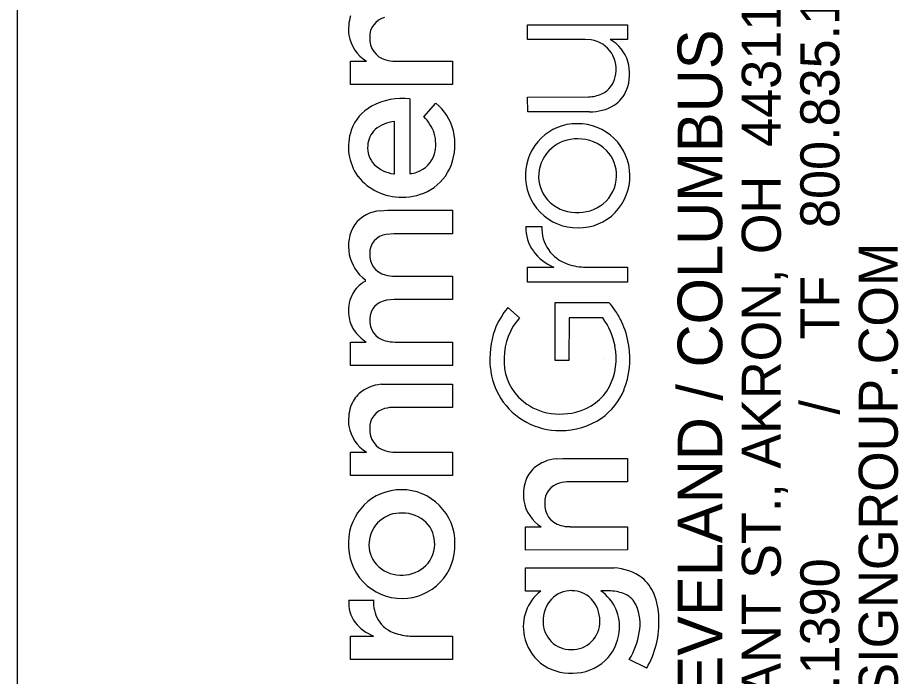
# Model space of a CAD drawing. Extents: x 0 to 34, y 0 to 22.
# Drawn here: x 32 to 33.125, y 3.094 to 3.936 of the extents above; entities that cross this region are included whole.
import ezdxf

# ---------------------------------------------------------------- set-up
doc = ezdxf.new("R2010")
doc.units = 0
doc.layers.add('SH_Border', color=7, linetype='Continuous')
doc.layers.add('SH_Data', color=7, linetype='Continuous')

msp = doc.modelspace()

# ---------------------------------------------------------------- linework, layer by layer
at = {"layer": 'SH_Border'}
msp.add_line((32, 0.5), (32, 21.5), dxfattribs=at)
at = {"layer": 'SH_Data'}
for p, q in [((32.6515, 3.908), (32.6515, 3.9267)), ((32.6515, 3.9267), (32.7791, 3.9266)), ((32.7791, 3.9266), (32.7791, 3.908)), ((32.7249, 3.908), (32.6515, 3.908)), ((32.7328, 3.9073), (32.7249, 3.908)), ((32.7791, 3.908), (32.7569, 3.908)), ((32.4254, 3.8503), (32.4254, 3.8802)), ((32.4254, 3.8802), (32.4455, 3.8802)), ((32.4822, 3.8802), (32.5557, 3.8802)), ((32.5557, 3.8802), (32.5557, 3.8504)), ((32.5557, 3.8504), (32.4254, 3.8503)), ((32.5011, 3.8321), (32.5012, 3.7366)), ((32.5188, 3.8093), (32.5342, 3.8266)), ((32.6515, 3.8344), (32.7291, 3.8345)), ((32.6517, 3.8154), (32.6515, 3.8344)), ((32.7307, 3.8154), (32.6517, 3.8154)), ((32.4814, 3.7364), (32.4814, 3.803)), ((32.4802, 3.7363), (32.4814, 3.7364)), ((32.4633, 3.6891), (32.4726, 3.6897)), ((32.4726, 3.6897), (32.5556, 3.6897)), ((32.5556, 3.6897), (32.5557, 3.6598)), ((32.6493, 3.6691), (32.6698, 3.6691)), ((32.4806, 3.6598), (32.471, 3.6588)), ((32.5557, 3.6598), (32.4806, 3.6598)), ((32.6515, 3.598), (32.6515, 3.617)), ((32.6515, 3.617), (32.6848, 3.617)), ((32.726, 3.617), (32.7791, 3.617)), ((32.7791, 3.617), (32.779, 3.598)), ((32.4444, 3.5992), (32.4446, 3.6007)), ((32.4822, 3.6055), (32.5557, 3.6055)), ((32.5557, 3.6055), (32.5557, 3.5757)), ((32.779, 3.598), (32.6515, 3.598)), ((32.4809, 3.5757), (32.4714, 3.5747)), ((32.5557, 3.5757), (32.4809, 3.5757)), ((32.6868, 3.5718), (32.7552, 3.5719)), ((32.6868, 3.4978), (32.6868, 3.5718)), ((32.6264, 3.5655), (32.6411, 3.5524)), ((32.7045, 3.5524), (32.7043, 3.4978)), ((32.7474, 3.5523), (32.7045, 3.5524)), ((32.4254, 3.4915), (32.4254, 3.5214)), ((32.4254, 3.5214), (32.4451, 3.5214)), ((32.4821, 3.5214), (32.5557, 3.5214)), ((32.5557, 3.5214), (32.5557, 3.4916)), ((32.75, 3.5), (32.75, 3.5)), ((32.5557, 3.4916), (32.4254, 3.4915)), ((32.7043, 3.4978), (32.6868, 3.4978)), ((32.4644, 3.4674), (32.4729, 3.4678)), ((32.4729, 3.4678), (32.5557, 3.4678)), ((32.5557, 3.4678), (32.5557, 3.438)), ((32.5557, 3.438), (32.4814, 3.438)), ((32.4254, 3.3509), (32.4254, 3.3807)), ((32.4254, 3.3807), (32.4455, 3.3807)), ((32.4822, 3.3807), (32.5557, 3.3807)), ((32.5557, 3.3807), (32.5557, 3.351)), ((32.6878, 3.3722), (32.6963, 3.3727)), ((32.6963, 3.3727), (32.7792, 3.3727)), ((32.7792, 3.3727), (32.7792, 3.3429)), ((32.5557, 3.351), (32.4254, 3.3509)), ((32.7792, 3.3429), (32.7048, 3.3428)), ((32.6489, 3.2557), (32.6489, 3.2855)), ((32.6489, 3.2855), (32.669, 3.2855)), ((32.7057, 3.2855), (32.7791, 3.2855)), ((32.7791, 3.2855), (32.7792, 3.2558)), ((32.7792, 3.2558), (32.6489, 3.2557)), ((32.6489, 3.2034), (32.6489, 3.2332)), ((32.6489, 3.2332), (32.7524, 3.2332)), ((32.7524, 3.2332), (32.7619, 3.2329)), ((32.6684, 3.2034), (32.6489, 3.2034)), ((32.7576, 3.2036), (32.7449, 3.2036)), ((32.423, 3.1919), (32.4545, 3.1919)), ((32.4254, 3.1159), (32.4254, 3.1458)), ((32.4254, 3.1458), (32.4547, 3.1458)), ((32.5041, 3.1458), (32.5557, 3.1457)), ((32.5557, 3.1457), (32.5556, 3.1159)), ((32.5556, 3.1159), (32.4254, 3.1159)), ((32.8036, 3.1049), (32.7812, 3.116))]:
    msp.add_line(p, q, dxfattribs=at)
for points in [[(32.7328, 3.9073), (32.7249, 3.908), (32.6515, 3.908), (32.6515, 3.9267), (32.7791, 3.9266), (32.7791, 3.908), (32.7569, 3.908)], [(32.4254, 3.8503), (32.4254, 3.8802), (32.4455, 3.8802)], [(32.4822, 3.8802), (32.5557, 3.8802), (32.5557, 3.8504), (32.4254, 3.8503)], [(32.5011, 3.8321), (32.5012, 3.7366)], [(32.5188, 3.8093), (32.5342, 3.8266)], [(32.7307, 3.8154), (32.6517, 3.8154), (32.6515, 3.8344), (32.7291, 3.8345)], [(32.4802, 3.7363), (32.4814, 3.7364), (32.4814, 3.803)], [(32.4633, 3.6891), (32.4726, 3.6897), (32.5556, 3.6897), (32.5557, 3.6598), (32.4806, 3.6598), (32.471, 3.6588)], [(32.6493, 3.6691), (32.6698, 3.6691)], [(32.6515, 3.598), (32.6515, 3.617), (32.6848, 3.617)], [(32.726, 3.617), (32.7791, 3.617), (32.779, 3.598), (32.6515, 3.598)], [(32.4444, 3.5992), (32.4446, 3.6007)], [(32.4822, 3.6055), (32.5557, 3.6055), (32.5557, 3.5757), (32.4809, 3.5757), (32.4714, 3.5747)], [(32.7474, 3.5523), (32.7045, 3.5524), (32.7043, 3.4978), (32.6868, 3.4978), (32.6868, 3.5718), (32.7552, 3.5719)], [(32.6264, 3.5655), (32.6411, 3.5524)], [(32.4254, 3.4915), (32.4254, 3.5214), (32.4451, 3.5214)], [(32.4821, 3.5214), (32.5557, 3.5214), (32.5557, 3.4916), (32.4254, 3.4915)], [(32.4644, 3.4674), (32.4729, 3.4678), (32.5557, 3.4678), (32.5557, 3.438), (32.4814, 3.438)], [(32.4254, 3.3509), (32.4254, 3.3807), (32.4455, 3.3807)], [(32.4822, 3.3807), (32.5557, 3.3807), (32.5557, 3.351), (32.4254, 3.3509)], [(32.6878, 3.3722), (32.6963, 3.3727), (32.7792, 3.3727), (32.7792, 3.3429), (32.7048, 3.3428)], [(32.6489, 3.2557), (32.6489, 3.2855), (32.669, 3.2855)], [(32.7057, 3.2855), (32.7791, 3.2855), (32.7792, 3.2558), (32.6489, 3.2557)], [(32.6684, 3.2034), (32.6489, 3.2034), (32.6489, 3.2332), (32.7524, 3.2332), (32.7619, 3.2329)], [(32.7576, 3.2036), (32.7449, 3.2036)], [(32.423, 3.1919), (32.4545, 3.1919)], [(32.4254, 3.1159), (32.4254, 3.1458), (32.4547, 3.1458)], [(32.5041, 3.1458), (32.5557, 3.1457), (32.5556, 3.1159), (32.4254, 3.1159)], [(32.8036, 3.1049), (32.7812, 3.116)]]:
    msp.add_lwpolyline(points, dxfattribs=at)
for centre, radius, start, end in [((32.4787, 3.9211), 0.056, 162.274, 187.7917), ((32.4787, 3.9211), 0.056, 162.274, 187.7917), ((32.4748, 3.9116), 0.025, 103.6868, 182.214), ((32.4748, 3.9116), 0.025, 103.6868, 182.214), ((32.4703, 3.9209), 0.0476, 188.9646, 238.6987), ((32.4703, 3.9209), 0.0476, 188.9646, 238.6987), ((32.4774, 3.9085), 0.0276, 175.5844, 255.1382), ((32.4774, 3.9085), 0.0276, 175.5844, 255.1382), ((32.7271, 3.87), 0.0377, 33.5008, 81.3295), ((32.7271, 3.87), 0.0377, 33.5008, 81.3295), ((32.7324, 3.8648), 0.0496, 17.6221, 60.3897), ((32.7324, 3.8648), 0.0496, 17.6221, 60.3897), ((32.4818, 3.9224), 0.0421, 254.0891, 270.5284), ((32.4818, 3.9224), 0.0421, 254.0891, 270.5284), ((32.7241, 3.8695), 0.0405, 346.5618, 31.7539), ((32.7241, 3.8695), 0.0405, 346.5618, 31.7539), ((32.7234, 3.8641), 0.0584, 339.162, 15.6148), ((32.7234, 3.8641), 0.0584, 339.162, 15.6148), ((32.7337, 3.8662), 0.0304, 294.6321, 348.4863), ((32.7337, 3.8662), 0.0304, 294.6321, 348.4863), ((32.7275, 3.8808), 0.0463, 271.952, 294.0894), ((32.7275, 3.8808), 0.0463, 271.952, 294.0894), ((32.739, 3.859), 0.042, 303.1039, 338.1561), ((32.739, 3.859), 0.042, 303.1039, 338.1561), ((32.4918, 3.7487), 0.0839, 83.6212, 118.2845), ((32.4918, 3.7487), 0.0839, 83.6212, 118.2845), ((32.494, 3.7763), 0.0644, 13.5328, 51.3627), ((32.494, 3.7763), 0.0644, 13.5328, 51.3627), ((32.4789, 3.7737), 0.0558, 118.8294, 160.6224), ((32.4789, 3.7737), 0.0558, 118.8294, 160.6224), ((32.7321, 3.8726), 0.0571, 268.627, 301.4778), ((32.7321, 3.8726), 0.0571, 268.627, 301.4778), ((32.4844, 3.7607), 0.0424, 94.0131, 130.8806), ((32.4844, 3.7607), 0.0424, 94.0131, 130.8806), ((32.4803, 3.7702), 0.0549, 19.0387, 45.4432), ((32.4803, 3.7702), 0.0549, 19.0387, 45.4432), ((32.487, 3.7707), 0.0644, 160.5214, 215.7815), ((32.487, 3.7707), 0.0644, 160.5214, 215.7815), ((32.477, 3.7709), 0.0298, 132.9855, 177.1802), ((32.477, 3.7709), 0.0298, 132.9855, 177.1802), ((32.7143, 3.7348), 0.0655, 89.4821, 178.7775), ((32.7143, 3.7348), 0.0655, 89.4821, 178.7775), ((32.7158, 3.7341), 0.0662, 0.4227, 90.7613), ((32.7158, 3.7341), 0.0662, 0.4227, 90.7613), ((32.4872, 3.7743), 0.047, 344.6072, 17.0067), ((32.4872, 3.7743), 0.047, 344.6072, 17.0067), ((32.4829, 3.7738), 0.0758, 339.3543, 13.3771), ((32.4829, 3.7738), 0.0758, 339.3543, 13.3771), ((32.714, 3.7324), 0.0485, 87.6883, 175.017), ((32.714, 3.7324), 0.0485, 87.6883, 175.017), ((32.7166, 3.7304), 0.0505, 44.912, 90.7591), ((32.7166, 3.7304), 0.0505, 44.912, 90.7591), ((32.4782, 3.7697), 0.0311, 175.0014, 223.2876), ((32.4782, 3.7697), 0.0311, 175.0014, 223.2876), ((32.499, 3.7718), 0.035, 288.0108, 343.5536), ((32.499, 3.7718), 0.035, 288.0108, 343.5536), ((32.7196, 3.7345), 0.0455, 358.3228, 43.8349), ((32.7196, 3.7345), 0.0455, 358.3228, 43.8349), ((32.4855, 3.7783), 0.0423, 225.0645, 262.797), ((32.4855, 3.7783), 0.0423, 225.0645, 262.797), ((32.4955, 3.7698), 0.0626, 300.9439, 338.7322), ((32.4955, 3.7698), 0.0626, 300.9439, 338.7322), ((32.5013, 3.7568), 0.0202, 269.7004, 294.8729), ((32.5013, 3.7568), 0.0202, 269.7004, 294.8729), ((32.7148, 3.7334), 0.0661, 177.5373, 270.9452), ((32.7148, 3.7334), 0.0661, 177.5373, 270.9452), ((32.7108, 3.7331), 0.0453, 175.5147, 221.4205), ((32.7108, 3.7331), 0.0453, 175.5147, 221.4205), ((32.4891, 3.7752), 0.0687, 217.7434, 271.6561), ((32.4891, 3.7752), 0.0687, 217.7434, 271.6561), ((32.7167, 3.7327), 0.0654, 269.3083, 1.6791), ((32.7167, 3.7327), 0.0654, 269.3083, 1.6791), ((32.7193, 3.7337), 0.0457, 308.9038, 359.3095), ((32.7193, 3.7337), 0.0457, 308.9038, 359.3095), ((32.492, 3.777), 0.0706, 269.2053, 300.3357), ((32.492, 3.777), 0.0706, 269.2053, 300.3357), ((32.714, 3.7373), 0.0505, 222.6626, 268.3733), ((32.714, 3.7373), 0.0505, 222.6626, 268.3733), ((32.7157, 3.7386), 0.0518, 266.5531, 308.6725), ((32.7157, 3.7386), 0.0518, 266.5531, 308.6725), ((32.4664, 3.644), 0.0452, 93.9112, 142.3072), ((32.4664, 3.644), 0.0452, 93.9112, 142.3072), ((32.4759, 3.6437), 0.0532, 148.2879, 233.9556), ((32.4759, 3.6437), 0.0532, 148.2879, 233.9556), ((32.6988, 3.6666), 0.0495, 177.1621, 216.2802), ((32.6988, 3.6666), 0.0495, 177.1621, 216.2802), ((32.7173, 3.6664), 0.0476, 176.7699, 252.1504), ((32.7173, 3.6664), 0.0476, 176.7699, 252.1504), ((32.4738, 3.635), 0.024, 96.7576, 181.6251), ((32.4738, 3.635), 0.024, 96.7576, 181.6251), ((32.4758, 3.6324), 0.026, 175.8157, 256.1672), ((32.4758, 3.6324), 0.026, 175.8157, 256.1672), ((32.7098, 3.6755), 0.0637, 216.9153, 246.8862), ((32.7098, 3.6755), 0.0637, 216.9153, 246.8862), ((32.7269, 3.6917), 0.0747, 251.1388, 269.3469), ((32.7269, 3.6917), 0.0747, 251.1388, 269.3469), ((32.4817, 3.6505), 0.045, 254.3463, 270.6103), ((32.4817, 3.6505), 0.045, 254.3463, 270.6103), ((32.4619, 3.5645), 0.0387, 139.5245, 154.847), ((32.4619, 3.5645), 0.0387, 139.5245, 154.847), ((32.4638, 3.5627), 0.0414, 117.9163, 139.243), ((32.4638, 3.5627), 0.0414, 117.9163, 139.243), ((32.4714, 3.5612), 0.0488, 156.0638, 187.3493), ((32.4714, 3.5612), 0.0488, 156.0638, 187.3493), ((32.4742, 3.5506), 0.0243, 96.5532, 179.949), ((32.4742, 3.5506), 0.0243, 96.5532, 179.949), ((32.725, 3.5394), 0.0444, 30.9891, 47.161), ((32.725, 3.5394), 0.0444, 30.9891, 47.161), ((32.7016, 3.5019), 0.0986, 139.7948, 159.137), ((32.7016, 3.5019), 0.0986, 139.7948, 159.137), ((32.6709, 3.5002), 0.1111, 25.3031, 33.9618), ((32.6709, 3.5002), 0.1111, 25.3031, 33.9618), ((32.4646, 3.5597), 0.0418, 186.5579, 213.3885), ((32.4646, 3.5597), 0.0418, 186.5579, 213.3885), ((32.4761, 3.5486), 0.0263, 175.722, 255.7863), ((32.4761, 3.5486), 0.0263, 175.722, 255.7863), ((32.699, 3.5008), 0.0775, 138.258, 179.7006), ((32.699, 3.5008), 0.0775, 138.258, 179.7006), ((32.6789, 3.501), 0.0856, 10.0751, 36.8319), ((32.6789, 3.501), 0.0856, 10.0751, 36.8319), ((32.6704, 3.4999), 0.1117, 8.8034, 25.3348), ((32.6704, 3.4999), 0.1117, 8.8034, 25.3348), ((32.4789, 3.5708), 0.0598, 214.7043, 235.6872), ((32.4789, 3.5708), 0.0598, 214.7043, 235.6872), ((32.7187, 3.4997), 0.1154, 161.1438, 185.6281), ((32.7187, 3.4997), 0.1154, 161.1438, 185.6281), ((32.4819, 3.5652), 0.0438, 253.6672, 270.1498), ((32.4819, 3.5652), 0.0438, 253.6672, 270.1498), ((32.6842, 3.5006), 0.0804, 333.4669, 11.0367), ((32.6842, 3.5006), 0.0804, 333.4669, 11.0367), ((32.6756, 3.4998), 0.1065, 338.2887, 9.2855), ((32.6756, 3.4998), 0.1065, 338.2887, 9.2855), ((32.6881, 3.4973), 0.0668, 176.6658, 223.6912), ((32.6881, 3.4973), 0.0668, 176.6658, 223.6912), ((32.6934, 3.497), 0.0899, 185.5077, 212.0129), ((32.6934, 3.497), 0.0899, 185.5077, 212.0129), ((32.4687, 3.4177), 0.0499, 94.9706, 130.2248), ((32.4687, 3.4177), 0.0499, 94.9706, 130.2248), ((32.4635, 3.426), 0.0402, 132.2238, 161.6823), ((32.4635, 3.426), 0.0402, 132.2238, 161.6823), ((32.6987, 3.4955), 0.0652, 282.8815, 331.8147), ((32.6987, 3.4955), 0.0652, 282.8815, 331.8147), ((32.6984, 3.4917), 0.0824, 305.0306, 337.6757), ((32.6984, 3.4917), 0.0824, 305.0306, 337.6757), ((32.6921, 3.4975), 0.0891, 212.7022, 270.714), ((32.6921, 3.4975), 0.0891, 212.7022, 270.714), ((32.6905, 3.5001), 0.0704, 224.0215, 253.88), ((32.6905, 3.5001), 0.0704, 224.0215, 253.88), ((32.4787, 3.4216), 0.056, 162.274, 187.7917), ((32.4787, 3.4216), 0.056, 162.274, 187.7917), ((32.4748, 3.4121), 0.025, 103.6868, 182.214), ((32.4748, 3.4121), 0.025, 103.6868, 182.214), ((32.4811, 3.392), 0.046, 89.6051, 105.3303), ((32.4811, 3.392), 0.046, 89.6051, 105.3303), ((32.6932, 3.5125), 0.0831, 254.4535, 283.9512), ((32.6932, 3.5125), 0.0831, 254.4535, 283.9512), ((32.6943, 3.4998), 0.0914, 269.3273, 304.1963), ((32.6943, 3.4998), 0.0914, 269.3273, 304.1963), ((32.4703, 3.4214), 0.0476, 188.9646, 238.6987), ((32.4703, 3.4214), 0.0476, 188.9646, 238.6987), ((32.4774, 3.409), 0.0276, 175.5844, 255.1382), ((32.4774, 3.409), 0.0276, 175.5844, 255.1382), ((32.4818, 3.4229), 0.0421, 254.0891, 270.5284), ((32.4818, 3.4229), 0.0421, 254.0891, 270.5284), ((32.6922, 3.3225), 0.0499, 94.9706, 130.2248), ((32.6922, 3.3225), 0.0499, 94.9706, 130.2248), ((32.6869, 3.3309), 0.0402, 132.2238, 161.6823), ((32.6869, 3.3309), 0.0402, 132.2238, 161.6823), ((32.7022, 3.3264), 0.056, 162.274, 187.7917), ((32.7022, 3.3264), 0.056, 162.274, 187.7917), ((32.7045, 3.2968), 0.046, 89.6051, 105.3303), ((32.7045, 3.2968), 0.046, 89.6051, 105.3303), ((32.4901, 3.2654), 0.0674, 89.8476, 179.6405), ((32.4901, 3.2654), 0.0674, 89.8476, 179.6405), ((32.4906, 3.2647), 0.0681, 359.5401, 90.2114), ((32.4906, 3.2647), 0.0681, 359.5401, 90.2114), ((32.6983, 3.3169), 0.025, 103.6868, 182.214), ((32.6983, 3.3169), 0.025, 103.6868, 182.214), ((32.6937, 3.3262), 0.0476, 188.9646, 238.6987), ((32.6937, 3.3262), 0.0476, 188.9646, 238.6987), ((32.7008, 3.3138), 0.0276, 175.5844, 255.1382), ((32.7008, 3.3138), 0.0276, 175.5844, 255.1382), ((32.4892, 3.2626), 0.0404, 87.0481, 175.5726), ((32.4892, 3.2626), 0.0404, 87.0481, 175.5726), ((32.492, 3.26), 0.043, 45.8426, 90.9801), ((32.492, 3.26), 0.043, 45.8426, 90.9801), ((32.4946, 3.2642), 0.0382, 357.8857, 44.159), ((32.4946, 3.2642), 0.0382, 357.8857, 44.159), ((32.7053, 3.3277), 0.0421, 254.0891, 270.5284), ((32.7053, 3.3277), 0.0421, 254.0891, 270.5284), ((32.4908, 3.2621), 0.0682, 176.8344, 270.4038), ((32.4908, 3.2621), 0.0682, 176.8344, 270.4038), ((32.4873, 3.2625), 0.0385, 175.1538, 221.1471), ((32.4873, 3.2625), 0.0385, 175.1538, 221.1471), ((32.4912, 3.2614), 0.0675, 270.0624, 2.3776), ((32.4912, 3.2614), 0.0675, 270.0624, 2.3776), ((32.4945, 3.2632), 0.0383, 308.2894, 359.4347), ((32.4945, 3.2632), 0.0383, 308.2894, 359.4347), ((32.4892, 3.2661), 0.0423, 223.0999, 268.8089), ((32.4892, 3.2661), 0.0423, 223.0999, 268.8089), ((32.491, 3.2679), 0.0442, 266.5651, 308.0608), ((32.491, 3.2679), 0.0442, 266.5651, 308.0608), ((32.7591, 3.1679), 0.065, 53.4034, 87.4906), ((32.7591, 3.1679), 0.065, 53.4034, 87.4906), ((32.7652, 3.1804), 0.0514, 21.6075, 50.5577), ((32.7652, 3.1804), 0.0514, 21.6075, 50.5577), ((32.7029, 3.1581), 0.0569, 127.3748, 192.2247), ((32.7029, 3.1581), 0.0569, 127.3748, 192.2247), ((32.7069, 3.1693), 0.0346, 88.473, 136.4256), ((32.7069, 3.1693), 0.0346, 88.473, 136.4256), ((32.7081, 3.1696), 0.0342, 44.2719, 90.4762), ((32.7081, 3.1696), 0.0342, 44.2719, 90.4762), ((32.7142, 3.1583), 0.0547, 352.1125, 55.923), ((32.7142, 3.1583), 0.0547, 352.1125, 55.923), ((32.7567, 3.1572), 0.0463, 65.0169, 88.8011), ((32.7567, 3.1572), 0.0463, 65.0169, 88.8011), ((32.7626, 3.1716), 0.0309, 26.2681, 63.803), ((32.7626, 3.1716), 0.0309, 26.2681, 63.803), ((32.7307, 3.1671), 0.0884, 1.1514, 21.3627), ((32.7307, 3.1671), 0.0884, 1.1514, 21.3627), ((32.4662, 3.1888), 0.0433, 175.8731, 216.3475), ((32.4662, 3.1888), 0.0433, 175.8731, 216.3475), ((32.5009, 3.1895), 0.0464, 176.9688, 209.6064), ((32.5009, 3.1895), 0.0464, 176.9688, 209.6064), ((32.7114, 3.166), 0.0401, 137.4674, 182.3324), ((32.7114, 3.166), 0.0401, 137.4674, 182.3324), ((32.7037, 3.166), 0.04, 358.5714, 43.5376), ((32.7037, 3.166), 0.04, 358.5714, 43.5376), ((32.7357, 3.1615), 0.0595, 349.3073, 23.4307), ((32.7357, 3.1615), 0.0595, 349.3073, 23.4307), ((32.4747, 3.1972), 0.0551, 218.0981, 248.7907), ((32.4747, 3.1972), 0.0551, 218.0981, 248.7907), ((32.4951, 3.1881), 0.0408, 211.9447, 253.2028), ((32.4951, 3.1881), 0.0408, 211.9447, 253.2028), ((32.7065, 3.1637), 0.0351, 178.8821, 271.0837), ((32.7065, 3.1637), 0.0351, 178.8821, 271.0837), ((32.7082, 3.164), 0.0355, 268.2788, 1.5502), ((32.7082, 3.164), 0.0355, 268.2788, 1.5502), ((32.7054, 3.1624), 0.1138, 329.6388, 3.26), ((32.7054, 3.1624), 0.1138, 329.6388, 3.26), ((32.7099, 3.1571), 0.0589, 313.742, 353.8554), ((32.7099, 3.1571), 0.0589, 313.742, 353.8554), ((32.7074, 3.1633), 0.0877, 327.3149, 351.5748), ((32.7074, 3.1633), 0.0877, 327.3149, 351.5748), ((32.5047, 3.2165), 0.0707, 252.4655, 269.573), ((32.5047, 3.2165), 0.0707, 252.4655, 269.573), ((32.7046, 3.157), 0.0584, 190.7518, 231.2892), ((32.7046, 3.157), 0.0584, 190.7518, 231.2892), ((32.7063, 3.1611), 0.0627, 232.4606, 272.5902), ((32.7063, 3.1611), 0.0627, 232.4606, 272.5902), ((32.7095, 3.159), 0.0605, 269.6361, 312.7088), ((32.7095, 3.159), 0.0605, 269.6361, 312.7088)]:
    msp.add_arc(centre, radius, start, end, dxfattribs=at)

# ---------------------------------------------------------------- texts
for s, height, p in [('800.835.1390', 0.049846, (33.0497, 3.6671)), ('450 GRANT ST., AKRON, OH  44311', 0.049846, (32.9749, 2.8374)), ('AKRON / CLEVELAND / COLUMBUS', 0.056969, (32.9001, 2.638)), ('ENVDESIGNGROUP.COM', 0.049846, (33.1244, 2.8374)), ('TF', 0.04985, (33.0497, 3.5246)), ('/  ', 0.04985, (33.0497, 3.4288)), ('330.375.1390', 0.049846, (33.0497, 2.8374))]:
    msp.add_text(s, height=height, rotation=90, dxfattribs=at).set_placement(p)

doc.saveas('drawing.dxf')
